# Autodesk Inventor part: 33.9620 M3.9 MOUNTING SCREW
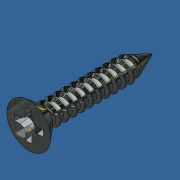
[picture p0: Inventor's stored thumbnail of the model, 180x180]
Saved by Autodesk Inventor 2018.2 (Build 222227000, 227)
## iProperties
Company: Microsoft
Created: 2013-02
Part Number: 33.9620 M3.9 MOUNTING SCREW
Material: Steel
Description: STEP AP203
Document SubType Name: Modeling
Designer: amoles
Appearance: Zinc
Mass: 1.04036 g
Surface Area: 2.84731 cm^2
Volume: 0.13253 cm^3
Density: 7.85 g/cm^3
Revision: ANY
Sending System: SolidWorks 2012
Preprocessor: SwSTEP 2.0
Title: 95844A325.step
Author: Admin
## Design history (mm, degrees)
node "Revolve2"
body "Solid1"
